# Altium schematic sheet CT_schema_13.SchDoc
size 388 x 278 mm
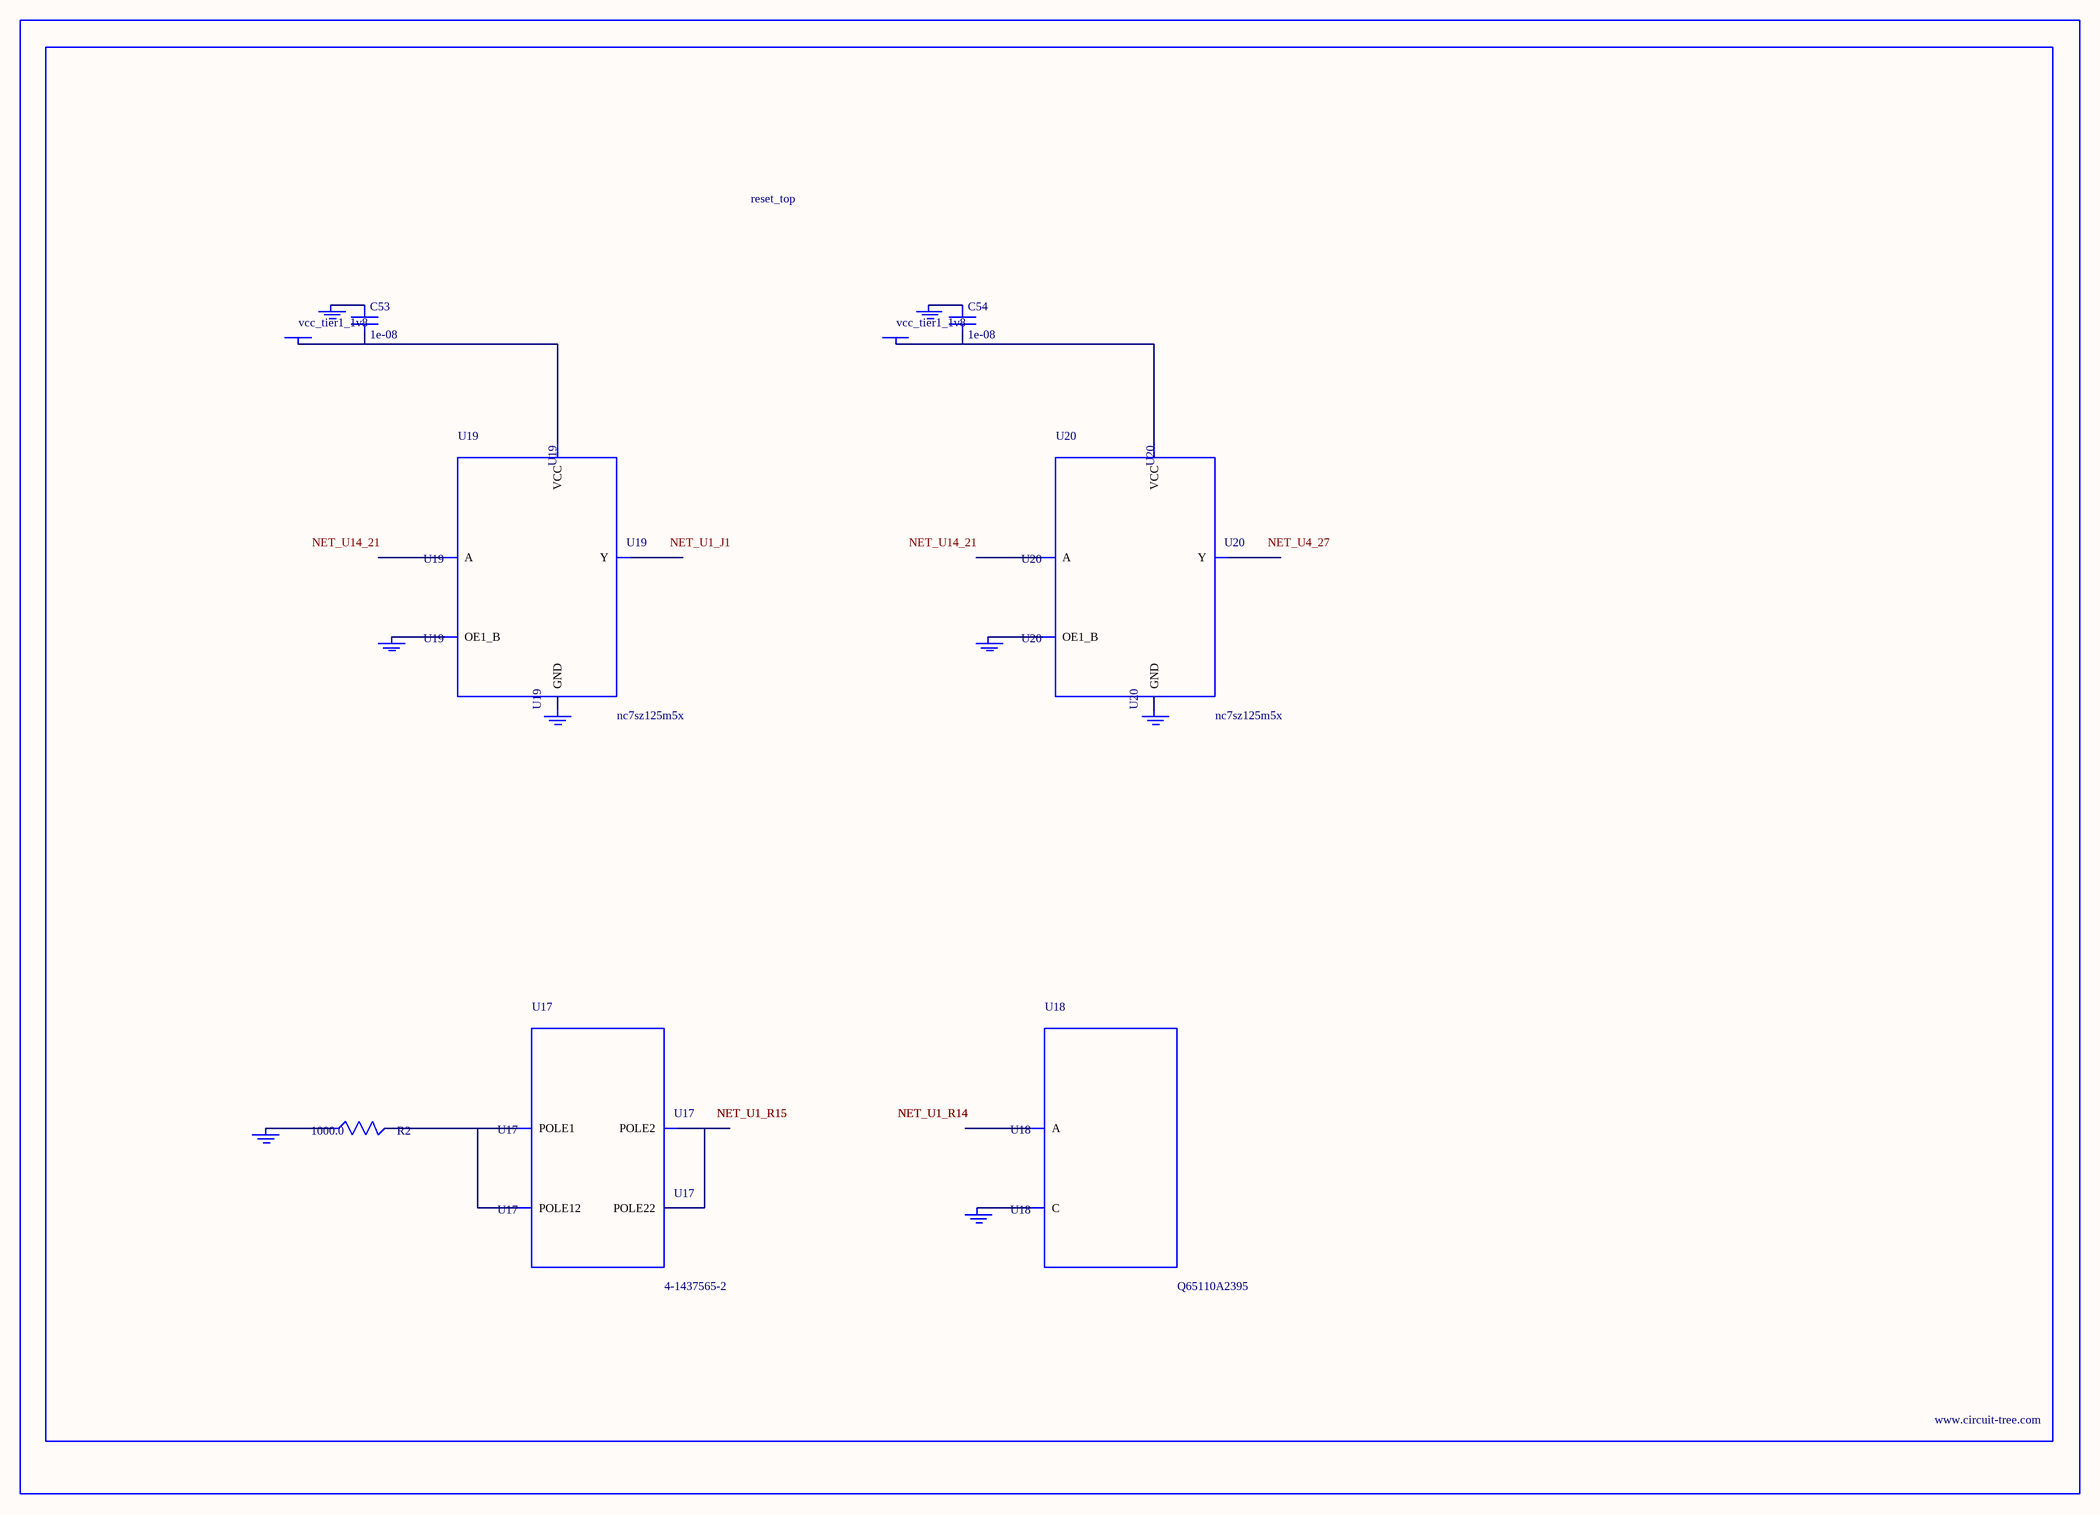
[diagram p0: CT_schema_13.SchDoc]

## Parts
BORDER12  (no value)
C53  1e-08  [C0402]
C54  1e-08  [C0402]
GND_INSTANCE_12_0  (no value)
GND_INSTANCE_12_1  (no value)
GND_INSTANCE_12_2  (no value)
GND_INSTANCE_12_3  (no value)
GND_INSTANCE_12_4  (no value)
GND_INSTANCE_12_5  (no value)
GND_INSTANCE_12_6  (no value)
GND_INSTANCE_12_7  (no value)
POWER_INSTANCE_12_0  vcc_tier1_1v8
POWER_INSTANCE_12_1  vcc_tier1_1v8
R2  1000.0  [R0603]
U17  4-1437565-2  [SW_4-1437565-2]
U18  Q65110A2395  [LGM67K-G1J2-24-Z]
U19  nc7sz125m5x  [NC7SZ125M5X]
U20  nc7sz125m5x  [NC7SZ125M5X]

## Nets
NetC53_1: C53.1 GND_INSTANCE_12_2.0(GND)
NetC53_2: C53.2 POWER_INSTANCE_12_0.0(PWR) U19.5(VCC)
NetC54_1: C54.1 GND_INSTANCE_12_5.0(GND)
NetC54_2: C54.2 POWER_INSTANCE_12_1.0(PWR) U20.5(VCC)
NetGND_INSTANCE_12_0_0: GND_INSTANCE_12_0.0(GND) R2.1
NetGND_INSTANCE_12_1_0: GND_INSTANCE_12_1.0(GND) U18.C
NetGND_INSTANCE_12_3_0: GND_INSTANCE_12_3.0(GND) U19.1(OE1_B)
NetGND_INSTANCE_12_4_0: GND_INSTANCE_12_4.0(GND) U19.3(GND)
NetGND_INSTANCE_12_6_0: GND_INSTANCE_12_6.0(GND) U20.1(OE1_B)
NetGND_INSTANCE_12_7_0: GND_INSTANCE_12_7.0(GND) U20.3(GND)
NetR2_2: R2.2 U17.1(POLE1) U17.2(POLE12)
NetU17_3: U17.3(POLE2) U17.4(POLE22)

Not connected (* = marked no-connect by the designer): U18 A; U19 2(A) 4(Y); U20 2(A) 4(Y)

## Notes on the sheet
- Labels drawn without touching a wire or pin: NET_U1_J1, NET_U4_27, NET_U14_21

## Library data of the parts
BORDER12 = BORDER_PAGE12
C53 C54 = C0402C103K3RAC
GND_INSTANCE_12_0-GND_INSTANCE_12_7 = GND
POWER_INSTANCE_12_0 POWER_INSTANCE_12_1 = PWR
R2 = RC0603JR-071KL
